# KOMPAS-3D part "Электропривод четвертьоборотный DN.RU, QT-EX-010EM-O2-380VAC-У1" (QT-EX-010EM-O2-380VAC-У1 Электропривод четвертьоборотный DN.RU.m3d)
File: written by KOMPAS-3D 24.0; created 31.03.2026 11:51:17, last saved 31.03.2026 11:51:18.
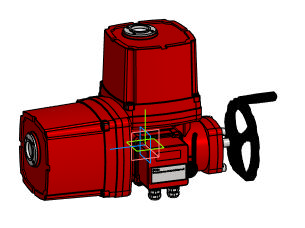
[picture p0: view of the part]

Document properties: Автор: DN.RU; Полное имя файла: D:\PROJECT CAD\DN.RU\...194\Исходники\QT-EX-010EM-O2-380VAC-У1\QT-EX-010EM-O2-380VAC-У1 Электропривод четвертьоборотный DN.RU.m3d

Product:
- Body: Твердое тело1  | qty 1
    Масса: 65.658095
- Part/product: Электропривод четвертьоборотный DN.RU  | designation QT-EX-010EM-O2-380VAC-У1
    Масса: 13
    Раздел спецификации: Прочие изделия
    Комментарий: D300-04901
    Примечание: D300-04901
    additional columns: Сталь

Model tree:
1. Твердое тело1  (labels: Твердое тело1)

Expressions: QT-EX-010EM-O2-380VAC-У1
